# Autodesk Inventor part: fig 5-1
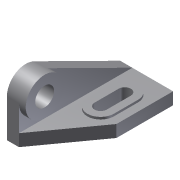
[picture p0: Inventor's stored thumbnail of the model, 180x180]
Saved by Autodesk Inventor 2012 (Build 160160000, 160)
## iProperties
Shininess: 64.0
Length Units: 11272
Angle Units: 11279
Time Units: 11290
Mass Units: 11283
Length Display Precision: 3
Angle Display Precision: 2
Compacted: True
Part Number: fig 5-1
Document SubType Name: Modeling
Created: 2003-01
Designer: Owner
Density: 1 g/cm^3
Material: Default
Density: 0.0
Volumn: 0.0
Area: 0.0
PropertySet Name: Model Information
Control State: 0
Master: False
Checked Out: False
Author: Owner
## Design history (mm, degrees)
sketch "Sketch1"
  geometry: L1 (-795.488, 2648.57)-(-795.488, 3054.97); L2 (1109.512, 1276.97)-(-795.488, 2648.57); L3 (3014.512, 1276.97)-(1109.512, 1276.97); L4 (3014.512, 3054.97)-(3014.512, 1276.97); L5 (-795.488, 3054.97)-(3014.512, 3054.97)
  constraints: 10 end point, 2 horizontal, 2 vertical, 1 other
  dimensions: "d1" = 3810 distance of L1.end L4.start; "d3" = 1778 distance of L4.start L3.start; "d5" = 1905 distance of L3.start L2.start; "d7" = 406.4 distance of L1.start L1.end
extrude "ExtrusionBlind1" new body sketch "Sketch1" distance "d8" = 406.4; taper "d9" = 0 deg
sketch "Sketch2"
  geometry: L1 (916.783, -1839.055)-(3810, -406.4); L2 (0, -406.4)-(0, -1270); L3 (3810, -406.4)-(0, -406.4); L4 (0, -406.4)-(3810, -406.4) reference; L5 (0, 0)-(0, -406.4) reference; A1 r 635 centre (635, -1270) between (0, -1270) and (916.783, -1839.055)
  constraints: 6 end point, 2 collinear, 2 point on circle, 2 tangent, 1 centre point, 1 horizontal, 1 vertical
  dimensions: "d14" = 1270 vertical distance of A1.centre L5.start; "d16" = 635 radius of A1
extrude "ExtrusionBlind2" join sketch "Sketch2" distance "d17" = 406.4; taper "d18" = 0 deg
sketch "Sketch3"
  geometry: C1 r 635 at (635, 1270); A1 r 635 centre (635, 1270) between (916.783, 1839.055) and (0, 1270) reference
  constraints: 1 centre point, 1 concentric
extrude "ExtrusionBlind3" join sketch "Sketch3" distance "d20" = 228.6; taper "d21" = 0 deg
sketch "Sketch4"
  geometry: L1 (1287.312, 1543.67)-(2100.112, 1543.67); L2 (2100.112, 2432.67)-(1287.312, 2432.67); A1 r 444.5 centre (2100.112, 1988.17) between (2100.112, 1543.67) and (2100.112, 2432.67); A2 r 444.5 centre (1287.312, 1988.17) between (1287.312, 2432.67) and (1287.312, 1543.67); 1 further point
  constraints: 4 end point, 4 point on circle, 4 tangent, 2 centre point, 2 horizontal
  dimensions: "d23" = 889 distance of L1.end L2.start; "d25" = 812.8 distance of L2.start L2.end; "d27" = 711.2 vertical distance of A1.centre point (3014.512, 1276.97); "d29" = 914.4 horizontal distance of A1.centre point (3014.512, 1276.97)
extrude "ExtrusionBlind4" join sketch "Sketch4" distance "d30" = 76.2; taper "d31" = 0 deg
sketch "Sketch5"
  geometry: L1 (2100.112, 2191.37)-(1287.312, 2191.37); L2 (1287.312, 1784.97)-(2100.112, 1784.97); A1 r 203.2 centre (1287.312, 1988.17) between (1287.312, 2191.37) and (1287.312, 1784.97); A2 r 203.2 centre (2100.112, 1988.17) between (2100.112, 1784.97) and (2100.112, 2191.37); A3 r 444.5 centre (2100.112, 1988.17) between (2100.112, 1543.67) and (2100.112, 2432.67) reference
  constraints: 4 end point, 4 point on circle, 4 tangent, 2 centre point, 2 horizontal, 1 concentric
  dimensions: "d35" = 812.8 distance of L2.start L2.end; "d37" = 406.4 distance of L2.start L1.end
extrude "ExtrusionThru1" cut sketch "Sketch5" stored distance "d38" = 3.302; taper "d39" = 0 deg
sketch "Sketch6"
  geometry: C1 r 635 at (0, 0) reference; 1 further point
hole "Hole1" sketch "Sketch6" at (0, 0) diameter "d40" = 635; stored, may be unused: countersink angle "d44" = 82 deg, drill point angle "d46" = 118 deg; dims "d41" = 12.7, "d42" = 9.525, "d43" = 6.35, "d45" = 19.05
body "Solid1"
other parameters: "d2" = 1778 (derived), "d4" = 1905 (derived), "d6" = 406.4 (derived), "d10" = 0, "d11" = 0, "d12" = 0 (derived), "d15" = 635 (derived), "d19" = 0, "d22" = 889 (derived), "d24" = 812.8 (derived), "d26" = 711.2 (derived), "d28" = 914.4 (derived), "d32" = 0, "d33" = 0, "d34" = 812.8 (derived), "d36" = 406.4 (derived)
